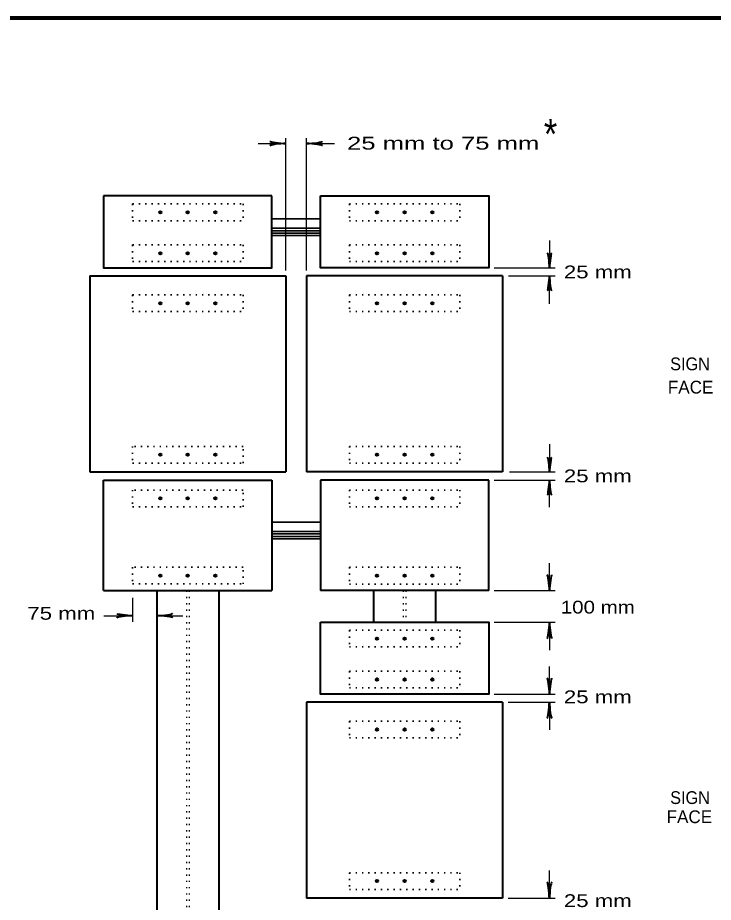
# Model space of a CAD drawing. Extents: x 851 to 1706, y -23 to 521.
# Drawn here: x 1193.3 to 1358.6, y 303.9 to 514.3 of the extents above; entities that cross this region are included whole.
import ezdxf
from ezdxf.enums import TextEntityAlignment as Align

# ---------------------------------------------------------------- set-up
doc = ezdxf.new("R2010")
doc.units = 0
doc.linetypes.add('DOTTED', pattern=[1.5, 0.3, -1.2])
doc.layers.add('1', color=7, linetype='Continuous', lineweight=35)

msp = doc.modelspace()

# ---------------------------------------------------------------- hatches: boundary and pattern name
at = {"layer": '1'}
for points in [[(1227.43, 467.983, 1), (1226.859, 467.983, 1)], [(1233.991, 467.983, 1), (1233.42, 467.983, 1)], [(1240.552, 467.983, 1), (1239.981, 467.983, 1)], [(1278.961, 467.983, 1), (1278.39, 467.983, 1)], [(1285.522, 467.983, 1), (1284.951, 467.983, 1)], [(1292.083, 467.983, 1), (1291.512, 467.983, 1)], [(1227.43, 458.251, 1), (1226.859, 458.251, 1)], [(1233.991, 458.251, 1), (1233.42, 458.251, 1)], [(1240.552, 458.251, 1), (1239.981, 458.251, 1)], [(1278.961, 458.251, 1), (1278.39, 458.251, 1)], [(1285.522, 458.251, 1), (1284.951, 458.251, 1)], [(1292.083, 458.251, 1), (1291.512, 458.251, 1)], [(1227.43, 446.359, 1), (1226.859, 446.359, 1)], [(1233.991, 446.359, 1), (1233.42, 446.359, 1)], [(1240.552, 446.359, 1), (1239.981, 446.359, 1)], [(1278.961, 446.359, 1), (1278.39, 446.359, 1)], [(1285.522, 446.359, 1), (1284.951, 446.359, 1)], [(1292.083, 446.359, 1), (1291.512, 446.359, 1)], [(1227.43, 410.328, 1), (1226.859, 410.328, 1)], [(1233.991, 410.328, 1), (1233.42, 410.328, 1)], [(1240.552, 410.328, 1), (1239.981, 410.328, 1)], [(1278.961, 410.328, 1), (1278.39, 410.328, 1)], [(1285.522, 410.328, 1), (1284.951, 410.328, 1)], [(1292.083, 410.328, 1), (1291.512, 410.328, 1)], [(1227.43, 399.94, 1), (1226.859, 399.94, 1)], [(1233.991, 399.94, 1), (1233.42, 399.94, 1)], [(1240.552, 399.94, 1), (1239.981, 399.94, 1)], [(1278.961, 399.94, 1), (1278.39, 399.94, 1)], [(1285.522, 399.94, 1), (1284.951, 399.94, 1)], [(1292.083, 399.94, 1), (1291.512, 399.94, 1)], [(1227.43, 381.583, 1), (1226.859, 381.583, 1)], [(1233.991, 381.583, 1), (1233.42, 381.583, 1)], [(1240.552, 381.583, 1), (1239.981, 381.583, 1)], [(1278.961, 381.569, 1), (1278.39, 381.569, 1)], [(1285.522, 381.569, 1), (1284.951, 381.569, 1)], [(1292.083, 381.569, 1), (1291.512, 381.569, 1)], [(1278.961, 366.616, 1), (1278.39, 366.616, 1)], [(1285.522, 366.616, 1), (1284.951, 366.616, 1)], [(1292.083, 366.616, 1), (1291.512, 366.616, 1)], [(1278.961, 356.883, 1), (1278.39, 356.883, 1)], [(1285.522, 356.883, 1), (1284.951, 356.883, 1)], [(1292.083, 356.883, 1), (1291.512, 356.883, 1)], [(1278.961, 344.992, 1), (1278.39, 344.992, 1)], [(1285.522, 344.992, 1), (1284.951, 344.992, 1)], [(1292.083, 344.992, 1), (1291.512, 344.992, 1)], [(1278.961, 308.961, 1), (1278.39, 308.961, 1)], [(1285.522, 308.961, 1), (1284.951, 308.961, 1)], [(1292.083, 308.961, 1), (1291.512, 308.961, 1)]]:
    msp.add_hatch(color=256, dxfattribs=at).paths.add_polyline_path(points)

# ---------------------------------------------------------------- linework, layer by layer
at = {"layer": '1', "lineweight": 25}
for p, q in [((1250.462, 484.331), (1257.023, 484.331)), ((1256.997, 454.15), (1256.997, 485.643)), ((1261.945, 454.15), (1261.945, 485.643)), ((1261.999, 484.331), (1268.56, 484.331)), ((1319.682, 461.258), (1319.682, 454.806)), ((1306.56, 454.806), (1320.994, 454.806)), ((1309.967, 452.838), (1320.994, 452.838)), ((1319.682, 446.214), (1319.682, 452.838)), ((1319.682, 412.885), (1319.682, 406.255)), ((1310.166, 406.255), (1320.994, 406.255)), ((1306.56, 404.287), (1320.994, 404.287)), ((1319.682, 397.841), (1319.682, 404.287)), ((1319.682, 378.015), (1319.682, 384.576)), ((1306.56, 378.043), (1320.994, 378.043)), ((1220.583, 376.289), (1220.583, 370.609)), ((1213.749, 372.065), (1220.638, 372.065)), ((1226.379, 372.065), (1232.557, 372.065)), ((1306.56, 370.498), (1320.994, 370.498)), ((1319.682, 370.434), (1319.682, 363.873)), ((1319.682, 353.439), (1319.682, 360)), ((1306.56, 353.439), (1320.994, 353.439)), ((1309.84, 351.471), (1320.994, 351.471)), ((1319.682, 351.471), (1319.682, 344.91)), ((1319.682, 304.887), (1319.682, 311.449)), ((1309.84, 304.887), (1320.994, 304.887))]:
    msp.add_line(p, q, dxfattribs=at)
at = {"layer": '1', "lineweight": 40}
for p, q in [((1253.717, 471.865), (1213.695, 471.865)), ((1210.414, 452.838), (1256.997, 452.838)), ((1210.414, 452.838), (1210.414, 406.255)), ((1256.997, 452.838), (1256.997, 406.255)), ((1308.528, 452.838), (1261.945, 452.838)), ((1261.945, 452.838), (1261.945, 406.255)), ((1308.528, 452.838), (1308.528, 406.255)), ((1210.414, 406.255), (1256.997, 406.255)), ((1308.528, 406.255), (1261.945, 406.255)), ((1213.695, 404.287), (1253.717, 404.287)), ((1213.695, 378.043), (1213.695, 404.287)), ((1253.717, 404.287), (1253.717, 378.043)), ((1305.248, 404.287), (1265.226, 404.287)), ((1265.226, 404.287), (1265.226, 378.043)), ((1305.248, 378.043), (1305.248, 404.287)), ((1213.694, 378.043), (1253.716, 378.043)), ((1213.695, 378.043), (1253.717, 378.043)), ((1226.324, 378.043), (1226.324, 276.675)), ((1241.087, 378.043), (1241.087, 276.675)), ((1305.248, 378.043), (1265.226, 378.043)), ((1305.248, 378.043), (1265.226, 378.043)), ((1277.856, 378.043), (1277.856, 370.498)), ((1292.618, 378.043), (1292.618, 370.498)), ((1308.528, 351.471), (1261.945, 351.471)), ((1261.945, 351.471), (1261.945, 304.887)), ((1308.528, 351.471), (1308.528, 304.887)), ((1308.528, 304.887), (1261.945, 304.887))]:
    msp.add_line(p, q, dxfattribs=at)
at = {"layer": '1', "linetype": 'DOTTED'}
for p, q in [((1220.583, 469.979), (1246.828, 469.979)), ((1220.583, 469.979), (1220.583, 465.987)), ((1246.828, 469.979), (1246.828, 465.987)), ((1272.115, 469.979), (1298.359, 469.979)), ((1272.115, 469.979), (1272.115, 465.987)), ((1298.359, 469.979), (1298.359, 465.987)), ((1220.583, 465.987), (1246.828, 465.987)), ((1272.115, 465.987), (1298.359, 465.987)), ((1220.583, 460.247), (1246.828, 460.247)), ((1220.583, 460.247), (1220.583, 456.255)), ((1246.828, 460.247), (1246.828, 456.255)), ((1272.115, 460.247), (1298.359, 460.247)), ((1272.115, 460.247), (1272.115, 456.255)), ((1298.359, 460.247), (1298.359, 456.255)), ((1220.583, 456.255), (1246.828, 456.255)), ((1272.115, 456.255), (1298.359, 456.255)), ((1220.583, 448.355), (1246.828, 448.355)), ((1220.583, 448.355), (1220.583, 444.363)), ((1246.828, 448.355), (1246.828, 444.363)), ((1272.115, 448.355), (1298.359, 448.355)), ((1272.115, 448.355), (1272.115, 444.363)), ((1298.359, 448.355), (1298.359, 444.363)), ((1220.583, 444.363), (1246.828, 444.363)), ((1272.115, 444.363), (1298.359, 444.363)), ((1272.115, 412.324), (1298.359, 412.324)), ((1272.115, 412.324), (1272.115, 408.333)), ((1298.359, 412.324), (1298.359, 408.333)), ((1272.115, 408.333), (1298.359, 408.333)), ((1272.115, 401.936), (1298.359, 401.936)), ((1272.115, 401.936), (1272.115, 397.944)), ((1298.359, 401.936), (1298.359, 397.944)), ((1272.115, 397.944), (1298.359, 397.944)), ((1272.115, 383.565), (1298.359, 383.565)), ((1272.115, 383.565), (1272.115, 379.574)), ((1298.359, 383.565), (1298.359, 379.574)), ((1272.115, 379.574), (1298.359, 379.574)), ((1272.115, 368.611), (1298.359, 368.611)), ((1272.115, 368.611), (1272.115, 364.62)), ((1298.359, 368.611), (1298.359, 364.62)), ((1272.115, 364.62), (1298.359, 364.62)), ((1272.115, 358.879), (1298.359, 358.879)), ((1272.115, 358.879), (1272.115, 354.888)), ((1298.359, 358.879), (1298.359, 354.888)), ((1272.115, 354.888), (1298.359, 354.888)), ((1272.115, 346.987), (1298.359, 346.987)), ((1272.115, 346.987), (1272.115, 342.996)), ((1298.359, 346.987), (1298.359, 342.996)), ((1272.115, 342.996), (1298.359, 342.996)), ((1272.115, 310.957), (1298.359, 310.957)), ((1272.115, 310.957), (1272.115, 306.965)), ((1298.359, 310.957), (1298.359, 306.965)), ((1272.115, 306.965), (1298.359, 306.965))]:
    msp.add_line(p, q, dxfattribs=at)
at = {"layer": '1', "linetype": 'DOTTED', "lineweight": 25}
for p, q in [((1298.359, 469.979), (1298.359, 465.987)), ((1298.359, 412.324), (1298.359, 408.333)), ((1298.359, 401.936), (1298.359, 397.944)), ((1298.359, 383.565), (1298.359, 379.601)), ((1298.359, 383.565), (1298.359, 379.574)), ((1233.377, 378.043), (1233.377, 276.675)), ((1234.033, 378.043), (1234.033, 276.675)), ((1284.909, 378.043), (1284.909, 370.498)), ((1285.565, 378.043), (1285.565, 370.498)), ((1298.359, 368.611), (1298.359, 364.62)), ((1298.359, 310.957), (1298.359, 306.965))]:
    msp.add_line(p, q, dxfattribs=at)
at = {"layer": '1'}
for p, q in [((1253.717, 466.425), (1265.226, 466.425)), ((1253.717, 464.21), (1265.226, 464.21)), ((1265.226, 463.609), (1253.717, 463.609)), ((1265.226, 463.008), (1253.717, 463.008)), ((1253.717, 462.434), (1265.226, 462.434)), ((1253.717, 394.308), (1265.226, 394.308)), ((1253.717, 392.094), (1265.226, 392.094)), ((1265.226, 391.493), (1253.717, 391.493)), ((1265.226, 390.864), (1253.717, 390.864)), ((1253.717, 390.317), (1265.226, 390.317))]:
    msp.add_line(p, q, dxfattribs=at)
at = {"layer": '1', "lineweight": 158}
msp.add_lwpolyline([(1699.744, 514.252), (908.044, 514.152), (908.144, -11.848)], dxfattribs=at)
at = {"layer": '1', "lineweight": 40}
msp.add_lwpolyline([(1213.695, 471.865), (1213.695, 454.806), (1253.717, 454.806), (1253.717, 471.865)], dxfattribs=at)
for points in [[(1265.226, 471.865), (1305.248, 471.865), (1305.248, 454.806), (1265.226, 454.806)], [(1265.226, 370.498), (1305.248, 370.498), (1305.248, 353.439), (1265.226, 353.439)]]:
    msp.add_lwpolyline(points, close=True, dxfattribs=at)
at = {"layer": '1', "linetype": 'DOTTED'}
for points in [[(1246.828, 412.324), (1220.583, 412.324), (1220.583, 408.333), (1246.828, 408.333)], [(1246.828, 401.936), (1220.583, 401.936), (1220.583, 397.944), (1246.828, 397.944)], [(1246.828, 383.565), (1220.583, 383.565), (1220.583, 379.601), (1246.828, 379.601)]]:
    msp.add_lwpolyline(points, close=True, dxfattribs=at)
at = {"layer": '1', "lineweight": 40}
for centre in [(1227.145, 467.983), (1233.706, 467.983), (1240.266, 467.983), (1278.676, 467.983), (1285.237, 467.983), (1291.798, 467.983), (1227.145, 458.251), (1233.706, 458.251), (1240.266, 458.251), (1278.676, 458.251), (1285.237, 458.251), (1291.798, 458.251), (1227.145, 446.359), (1233.706, 446.359), (1240.266, 446.359), (1278.676, 446.359), (1285.237, 446.359), (1291.798, 446.359), (1227.145, 410.328), (1233.706, 410.328), (1240.266, 410.328), (1278.676, 410.328), (1285.237, 410.328), (1291.798, 410.328), (1227.145, 399.94), (1233.706, 399.94), (1240.266, 399.94), (1278.676, 399.94), (1285.237, 399.94), (1291.798, 399.94), (1227.145, 381.583), (1233.706, 381.583), (1240.266, 381.583), (1278.676, 381.569), (1285.237, 381.569), (1291.798, 381.569), (1278.676, 366.616), (1285.237, 366.616), (1291.798, 366.616), (1278.676, 356.883), (1285.237, 356.883), (1291.798, 356.883), (1278.676, 344.992), (1285.237, 344.992), (1291.798, 344.992), (1278.676, 308.961), (1285.237, 308.961), (1291.798, 308.961)]:
    msp.add_circle(centre, 0.286, dxfattribs=at)
for centre, major_axis, ratio, start_param, end_param in [((1255.582, 483.974), (2.343, 0.205), 0.122415, 0.8963533, 3.1415927), ((1255.582, 483.974), (2.343, 0.205), 0.122415, 0.8963533, 3.1415927), ((1255.543, 484.615), (2.305, -0.23), 0.07063, 3.1407148, 5.41811), ((1255.543, 484.615), (2.305, -0.23), 0.07063, 3.1407148, 5.41811), ((1263.418, 484.699), (-2.343, -0.205), 0.122415, 0.8963533, 3.1415927), ((1263.456, 484.059), (-2.305, 0.23), 0.07063, 3.1407148, 5.41811), ((1319.35, 456.116), (0.187, -2.143), 0.122415, 0.8963533, 3.1415927), ((1319.936, 456.151), (-0.211, -2.108), 0.07063, 3.1407148, 5.41811), ((1319.428, 451.493), (0.211, 2.108), 0.07063, 3.1407148, 5.41811), ((1320.013, 451.529), (-0.187, 2.143), 0.122415, 0.8963533, 3.1415927), ((1319.35, 407.564), (0.187, -2.143), 0.122415, 0.8963533, 3.1415927), ((1319.936, 407.6), (-0.211, -2.108), 0.07063, 3.1407148, 5.41811), ((1319.428, 402.942), (0.211, 2.108), 0.07063, 3.1407148, 5.41811), ((1320.013, 402.977), (-0.187, 2.143), 0.122415, 0.8963533, 3.1415927), ((1319.307, 379.437), (0.205, -2.343), 0.122415, 0.8963533, 3.1415927), ((1319.947, 379.475), (-0.23, -2.305), 0.07063, 3.1407148, 5.41811), ((1219.164, 372.356), (2.305, -0.23), 0.07063, 3.1407148, 5.41811), ((1219.164, 372.356), (2.305, -0.23), 0.07063, 3.1407148, 5.41811), ((1227.807, 372.441), (-2.343, -0.205), 0.122415, 0.8963533, 3.1415927), ((1219.202, 371.716), (2.343, 0.205), 0.122415, 0.8963533, 3.1415927), ((1219.202, 371.716), (2.343, 0.205), 0.122415, 0.8963533, 3.1415927), ((1227.845, 371.801), (-2.305, 0.23), 0.07063, 3.1407148, 5.41811), ((1319.307, 369.012), (0.205, 2.343), 0.122415, 3.1415927, 5.386832), ((1319.947, 368.974), (-0.23, 2.305), 0.07063, 0.8650754, 3.1424706), ((1319.307, 354.877), (0.205, -2.343), 0.122415, 0.8963533, 3.1415927), ((1319.307, 354.877), (0.205, -2.343), 0.122415, 0.8963533, 3.1415927), ((1319.947, 354.915), (-0.23, -2.305), 0.07063, 3.1407148, 5.41811), ((1319.947, 354.915), (-0.23, -2.305), 0.07063, 3.1407148, 5.41811), ((1319.392, 350.006), (0.23, 2.305), 0.07063, 3.1407148, 5.41811), ((1319.392, 350.006), (0.23, 2.305), 0.07063, 3.1407148, 5.41811), ((1320.032, 350.045), (-0.205, 2.343), 0.122415, 0.8963533, 3.1415927), ((1320.032, 350.045), (-0.205, 2.343), 0.122415, 0.8963533, 3.1415927), ((1319.392, 306.364), (0.23, -2.305), 0.07063, 0.8650754, 3.1424706), ((1319.392, 306.364), (0.23, -2.305), 0.07063, 0.8650754, 3.1424706), ((1320.032, 306.325), (-0.205, -2.343), 0.122415, 3.1415927, 5.386832), ((1320.032, 306.325), (-0.205, -2.343), 0.122415, 3.1415927, 5.386832)]:
    msp.add_ellipse(centre, major_axis=major_axis, ratio=ratio, start_param=start_param, end_param=end_param, dxfattribs=at)

# ---------------------------------------------------------------- texts
at = {"layer": '1'}
for s, height, width, p in [('*', 7.2, 0.85, (1319.933, 483.001)), ('25 mm to 75 mm', 3.037, 1.5, (1294.412, 482.894)), ('25 mm', 3.037, 1.3, (1331.165, 452.276)), ('SIGN', 3.037, 0.95, (1353.088, 430.412)), ('25 mm', 3.037, 1.3, (1331.165, 403.779)), ('100 mm', 3.037, 1.2, (1331.164, 372.576)), ('75 mm', 3.037, 1.3, (1203.633, 371.103)), ('25 mm', 3.037, 1.3, (1331.165, 351.245)), ('SIGN', 3.037, 0.95, (1353.088, 327.283)), ('25 mm', 3.037, 1.3, (1331.165, 302.778))]:
    msp.add_text(s, height=height, dxfattribs=dict(at, width=width)).set_placement(p, align=Align.CENTER)
for p in [(1353.228, 424.884), (1352.934, 322.737)]:
    msp.add_text('FACE', height=3.037, dxfattribs=at).set_placement(p, align=Align.CENTER)

doc.saveas('drawing.dxf')
